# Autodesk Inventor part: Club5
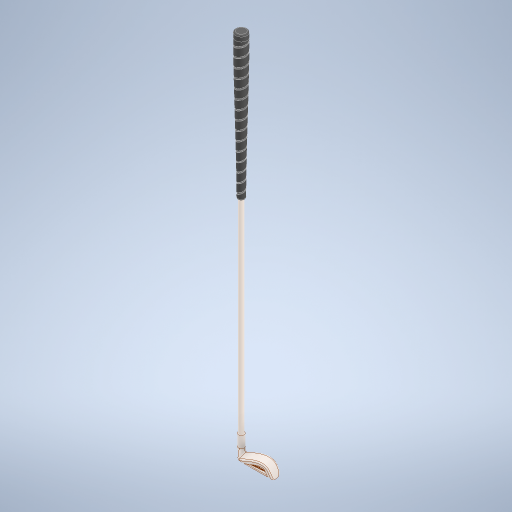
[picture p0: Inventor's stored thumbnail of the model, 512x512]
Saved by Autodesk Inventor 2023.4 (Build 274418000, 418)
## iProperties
Created: 2009-07
Part Number: Club5
Material: Générique
Document SubType Name: Modeling
Designer: bruno
Density: 1 g/cm^3
Appearance: Par défaut
Author: bruno
Sending System: SolidWorks 2013
Last Author: PAVEL
Last Saved: 2013-05-30
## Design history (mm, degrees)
node "golf club.SLDPRT"
node "Solide1"
feature "Shaft"
node "Solide2"
feature "Grip"
node "Solide3"
feature "Clubhead"
